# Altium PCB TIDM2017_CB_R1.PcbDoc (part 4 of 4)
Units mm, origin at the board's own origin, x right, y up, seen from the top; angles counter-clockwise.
Board outline 120 x 77 mm, 4 copper layers (Top Layer, Layer 1, Layer 2, Bottom Layer), stack 1.856 mm thick; 246 components, 167 nets, 1255 pads, 326 vias.
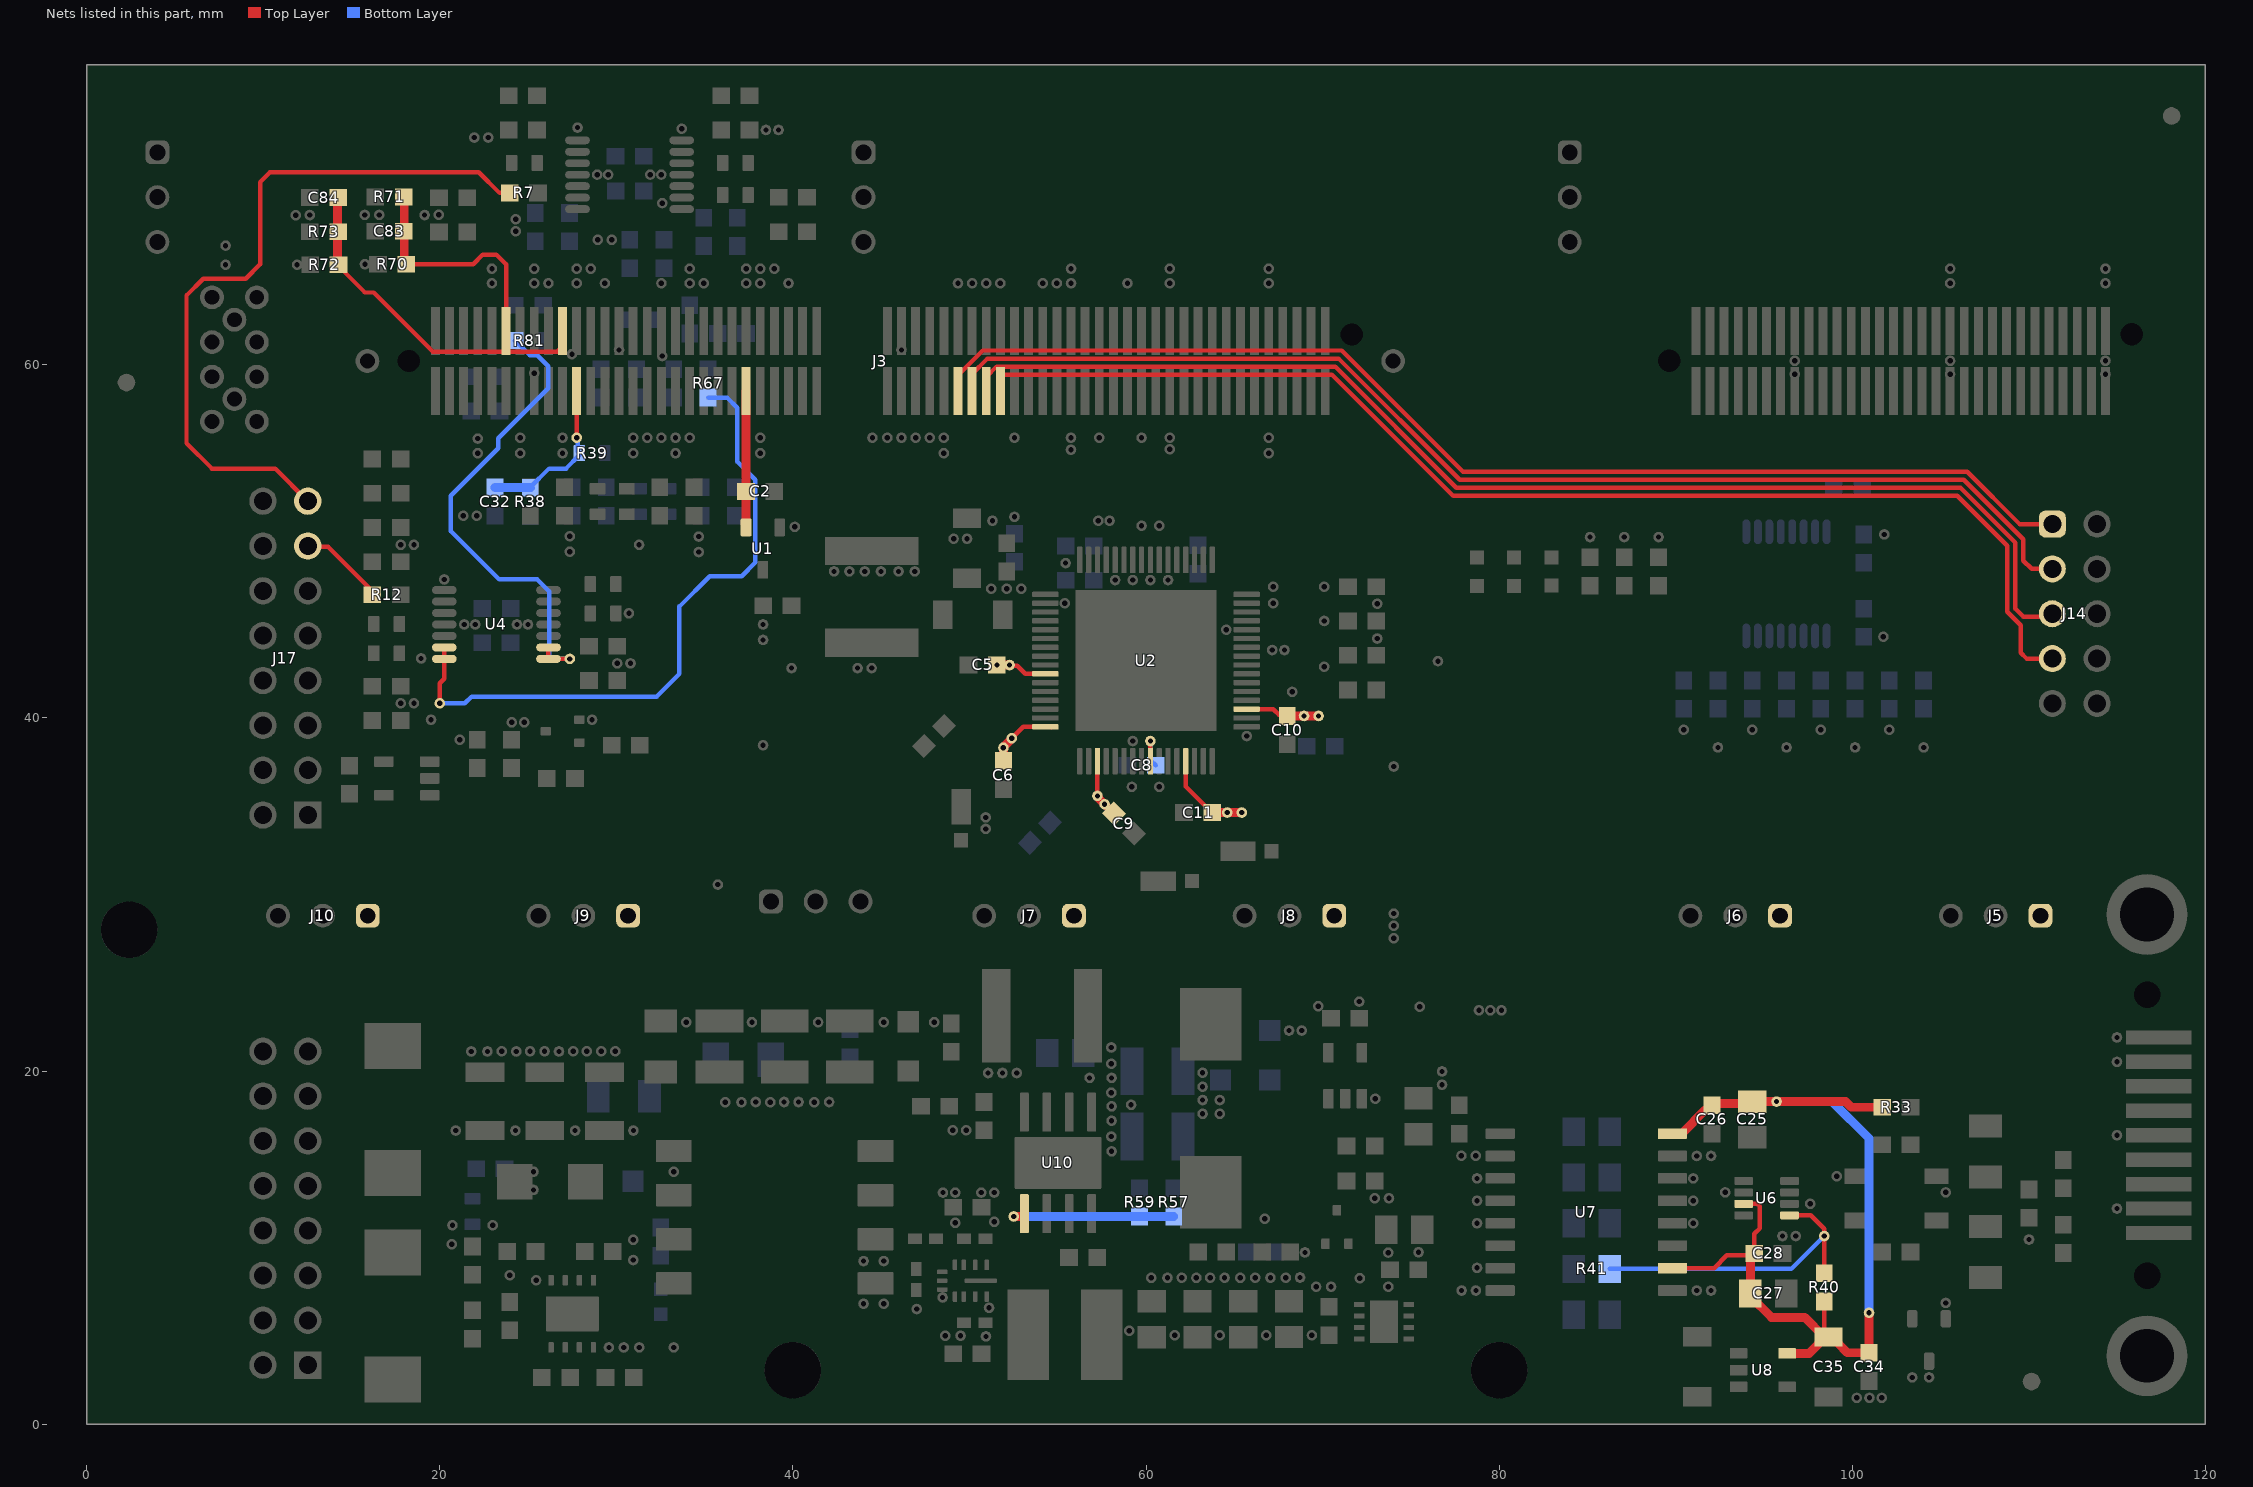
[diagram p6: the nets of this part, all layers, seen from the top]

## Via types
v1: diameter 0.6, hole 0.3, Top Layer to Bottom Layer, 276 vias
v2: diameter 0.5, hole 0.2, Top Layer to Bottom Layer, 40 vias
v3: diameter 0.63, hole 0.33, Top Layer to Bottom Layer, tented both sides, 6 vias
v4: diameter 0.5, hole 0.2, Top Layer to Bottom Layer, tented both sides, 4 vias

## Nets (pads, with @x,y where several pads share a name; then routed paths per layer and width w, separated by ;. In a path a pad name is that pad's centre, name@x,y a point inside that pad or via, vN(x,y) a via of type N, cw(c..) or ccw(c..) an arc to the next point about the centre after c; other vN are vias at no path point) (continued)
NetR57_1: pad.2@52.51,11.761 R57.1 R59.2 U10.5 | length 9.8
  Top Layer w0.5: pad.2@52.51,11.761 53.11,11.761 U10.5@53.11,11.924
  Bottom Layer w0.5: pad.2@52.51,11.761 R59.2@59.634,11.761 R57.1@61.573,11.761
NetR67_1: pad.2@20,40.829 R67.1 U4.6 U4.7 | length 37.8
  Top Layer w0.254: pad.2@20,40.829 20,41.961 20.255,42.215 U4.7@20.255,43.344 U4.6@20.255,43.994
  Bottom Layer w0.254: pad.2@20,40.829 21.416,40.829 21.799,41.212 32.287,41.212 33.574,42.499 33.574,46.316 35.287,48.029 37.096,48.029 37.875,48.808 37.875,53.492 36.844,54.523 36.844,57.574 36.27,58.148 R67.1@35.194,58.148
NetR81_1: pad.2@27.364,43.344 R81.1 U4.8 U4.9 | length 27.9
  Top Layer w0.254: U4.9@26.155,43.994 U4.8@26.155,43.344 pad.2@27.364,43.344
  Bottom Layer w0.254: R81.1@24.253,61.375 24.278,61.375 25.103,60.55 25.521,60.55 26.15,59.922 26.15,58.682 23.306,55.838 23.306,55.269 20.625,52.588 20.625,50.588 23.369,47.844 25.514,47.844 26.184,47.173 26.184,43.493 26.333,43.344 pad.2@27.364,43.344
P5V_BATT: C25.1 C26.1 C27.1 C28.1 C34.1 C35.1 pad.2@95.716,18.271 pad.2@100.955,6.31 R33.2 R40.2 U6.3 U7.10 U7.16 U8.5 | length 54.6
  Top Layer w0.254: U7.10@89.816,8.838 92.182,8.838 92.901,9.557 94.344,9.557 C28.1@94.452,9.665 94.452,10.775 94.777,11.1 94.777,12.328 94.628,12.477 U6.3@93.851,12.477 ; R40.2@98.418,6.948 98.418,5.179 C35.1@98.66,4.936
  Top Layer w0.5: U7.16@89.816,16.458 90.341,16.458 91.688,17.805 91.834,17.805 92.059,18.03 C26.1@92.059,18.055 92.167,18.163 94.236,18.163 C25.1@94.344,18.271 99.633,18.271 99.957,17.948 R33.2@101.705,17.948 ; C28.1@94.344,9.557 94.236,9.449 94.236,7.235 95.428,6.043 97.303,6.043 98.41,4.936 98.11,4.636 98.11,4.553 97.567,4.009 U8.5@96.317,4.009 ; C35.1@98.66,4.936 98.91,4.936 99.21,4.636 99.21,4.565 99.73,4.045 C34.1@100.955,4.045 pad.2@100.955,6.31
  Bottom Layer w0.5: pad.2@95.716,18.271 98.878,18.271 100.955,16.194 pad.2@100.955,6.31
POS_LDO_SENSE: C83.2 J3.12 R70.2 R71.2 | length 13.9
  Top Layer w0.254: R70.2@18.022,65.705 21.889,65.705 22.434,66.25 23.205,66.25 23.75,65.705 J3.12@23.75,61.919 J3.12@23.832,61.836
  Top Layer w0.5: R71.2@17.947,69.509 17.984,69.472 17.984,65.742 R70.2@18.022,65.705
SHA: C5.1 J10.1 pad.2@51.562,43 pad.2@52.273,42.999 U2.26 | length 3
  Top Layer w0.254: pad.2@52.273,42.999 52.321,42.952 52.704,42.952 53.156,42.5 U2.26@54.3,42.5
  Top Layer w0.5: pad.2@51.562,43 C5.1@51.575,43 ; pad.2@51.562,43 pad.2@52.273,42.999
SHB: C8.1 J7.1 pad.2@60.25,38.692 U2.41 | length 2.6
  Top Layer w0.254: U2.41@60.25,37.55 pad.2@60.25,38.692
  Bottom Layer w0.254: pad.2@60.25,38.692 60.25,37.621 C8.1@60.55,37.321
SHC: C10.1 J6.1 pad.2@68.95,40.111 pad.2@69.776,40.111 U2.51 | length 4.2
  Top Layer w0.254: U2.51@65.7,40.5 67.215,40.5 67.529,40.186 67.929,40.186 C10.1@68.004,40.111
  Top Layer w0.5: C10.1@68.004,40.111 pad.2@68.95,40.111 pad.2@69.776,40.111
SLA: C6.1 J9.1 pad.2@51.922,38.317 pad.2@52.397,38.853 U2.32 | length 4
  Top Layer w0.254: pad.2@52.397,38.853 53.044,39.5 U2.32@54.3,39.5 54.604,39.5 U2.32@54.627,39.477
  Top Layer w0.5: C6.1@51.922,37.567 pad.2@51.922,38.317 51.922,38.344 52.378,38.8 52.378,38.834 pad.2@52.397,38.853
SLB: C9.1 J8.1 pad.2@57.25,35.583 pad.2@57.654,35.112 U2.35 | length 3.4
  Top Layer w0.254: pad.2@57.25,35.583 U2.35@57.25,37.55
  Top Layer w0.5: pad.2@57.25,35.583 57.25,35.556 57.3,35.506 57.3,35.466 C9.1@58.184,34.582
SLC: C11.1 J5.1 pad.2@64.604,34.642 pad.2@65.43,34.642 U2.45 | length 5.2
  Top Layer w0.254: U2.45@62.25,37.55 62.25,36.117 63.725,34.642 C11.1@63.75,34.642
  Top Layer w0.5: C11.1@63.75,34.642 pad.2@65.43,34.642
SPIA_CLK: J3.71 J14.5 | length 69.5
  Top Layer w0.254: J3.71@50.95,58.519 50.982,58.55 50.982,59.351 51.537,59.906 70.717,59.906 77.58,53.043 106.136,53.043 109.242,49.937 109.242,46.199 109.696,45.745 111.177,45.745 J14.5@111.335,45.903
SPIA_SIMO: J3.67 J14.1 | length 67.5
  Top Layer w0.254: J3.67@49.35,58.519 49.35,59.412 50.751,60.814 71.093,60.814 77.956,53.951 106.513,53.951 109.481,50.983 J14.1@111.335,50.983
SPIA_SOMI: J3.69 J14.3 | length 68.2
  Top Layer w0.254: J3.69@50.15,58.519 50.16,58.529 50.16,59.5 51.021,60.36 70.905,60.36 77.768,53.497 106.324,53.497 109.696,50.125 109.696,48.912 110.166,48.443 J14.3@111.335,48.443
SPIA_STE: J3.73 J14.7 | length 70.3
  Top Layer w0.254: J3.73@51.846,58.615 J3.73@51.75,58.519 51.725,58.543 51.725,59.244 51.933,59.452 70.529,59.452 77.392,52.589 105.948,52.589 108.788,49.749 108.788,46.011 109.548,45.252 109.548,43.693 109.878,43.363 J14.7@111.335,43.363
THROTTLE_1: J17.15 R7.1 | length 41.4
  Top Layer w0.254: J17.15@12.52,52.28 10.675,54.125 7.094,54.125 5.65,55.569 5.65,63.93 6.604,64.884 8.999,64.884 9.815,65.7 9.815,70.35 10.38,70.915 22.208,70.915 23.383,69.74 24.037,69.74 24.037,69.816 R7.1@23.839,70.014
THROTTLE_2: J17.13 R12.1 | length 5
  Top Layer w0.254: J17.13@12.52,49.74 12.575,49.685 13.676,49.685 16.257,47.104 R12.1@16.257,46.979
THROTTLE_LDO_SENSE: C84.2 J3.20 R72.2 R73.2 | length 19.7
  Top Layer w0.254: R72.2@14.187,65.671 14.187,65.546 14.385,65.348 14.51,65.348 15.76,64.099 16.257,64.099 19.6,60.757 26.638,60.757 26.95,61.068 J3.20@26.95,61.919
  Top Layer w0.5: R72.2@14.187,65.671 14.212,65.696 14.212,69.451 C84.2@14.238,69.476
VDC: C32.2 J3.21 pad.2@27.75,55.875 R38.2 R39.2 | length 9.3
  Top Layer w0.254: pad.2@27.75,55.875 J3.21@27.75,58.519
  Bottom Layer w0.254: R38.2@25.128,53.044 25.128,53.069 26.184,54.125 27.15,54.125 27.9,54.875 R39.2@27.9,55 27.816,55.084 27.816,55.809 pad.2@27.75,55.875
  Bottom Layer w0.5: C32.2@23.125,53.05 23.128,53.047 25.125,53.047 R38.2@25.128,53.044
VIO: pad.2@98.418,10.653 R40.1 R41.2 U6.5 | length 17.7
  Top Layer w0.254: U6.5@96.451,11.827 97.66,11.827 98.418,11.069 pad.2@98.418,10.653 R40.1@98.418,8.548
  Bottom Layer w0.254: R41.2@86.266,8.788 96.552,8.788 pad.2@98.418,10.653
VREF: C2.2 J3.45 U1.2 | length 7.8
  Top Layer w0.5: U1.2@37.344,50.76 37.35,50.766 J3.45@37.35,58.519
pads on no net: FID1.1 FID2.1 FID3.1 J3.1 J3.2 J3.14 J3.17 J3.23 J3.30 J3.32 J3.36 J3.39 J3.41 J3.42 J3.43 J3.44 J3.54 J3.56 J3.62 J3.64 J3.66 J3.76 J3.78 J3.85 J3.86 J3.88 J3.89 J3.90 J3.91 J3.96 J3.100 J3.102 J3.104 J3.105 J3.106 J3.107 J3.108 J3.109 J3.113 J3.114 J3.115 J3.116 J3.117 J3.118 J3.119 J3.181 J3.182 J3.185 J3.186 J4.61 J4.62 J4.121 J4.122 J4.123 J4.124 J4.125 J4.126 J4.127 J4.128 J4.129 J4.130 J4.131 J4.132 J4.133 J4.134 J4.136 J4.137 J4.138 J4.139 J4.140 J4.141 J4.142 J4.143 J4.144 J4.145 J4.146 J4.147 J4.148 J4.149 J4.150 J4.151 J4.152 J4.153 J4.154 J4.155 J4.156 J4.159 J4.160 J4.161 J4.162 J4.163 J4.164 J4.165 J4.166 J4.167 J4.168 J4.169 J4.170 J4.171 J4.172 J4.173 J4.174 J4.175 J4.176 J4.177 J4.178 J5.3 J8.3 J9.3 J15.4 J15.5 J15.8 J15.MH LBL1.0 U2.16 U2.21 U2.22 U2.24 U2.29 U2.30 U2.37 U2.38 U2.43 U2.47 U2.48 U2.54 U2.55 U2.56 U2.57 U4.12 U4.13 U4.14 U5.1 U5.3 U5.14 U5.16 U7.6 U7.11 U8.2 U9.9@26.749,6.246 U9.9@28.259,6.246 U10.6 U11.8

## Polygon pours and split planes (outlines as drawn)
SLC on Layer 1 "LAYER_1_SLC_P006" (solid, remove dead copper, pour order 6): 61.3,33.68 63.75,31.23 63.75,31.21 69.457,31.21 71.927,33.68 101.548,33.68 104.316,30.912 104.316,27.528 111.936,27.528 111.936,30.27 104.956,37.25 66.195,37.25 65.1,38.345 61.3,38.344
GND on Layer 1 "LAYER_1_GND_P041" (solid, remove dead copper, pour order 41): 1.375,10.061 17.832,10.061 17.832,21.477 19.883,23.528 34.484,23.528 34.484,17.666 34.634,17.516 43.687,17.516 43.687,5.003 44.961,3.729 74.718,3.729 77.913,6.923 79.791,6.923 79.791,18.687 83.56,22.456 110.923,22.456 113.605,25.138 113.605,31.261 118.594,36.251 118.594,75.971 1.375,75.971 1.375,27.528 9.021,27.575 9.021,31.093 10.474,32.545 16.886,32.545 21.091,36.75 41.209,36.75 41.209,36.766 48.98,44.536 52.761,44.536 53.496,43.802 55.636,43.802 55.636,47.206 55.998,47.568 63.898,47.568 64.234,47.233 64.234,39.61 66.355,37.488 105.242,37.488 112.063,30.668 112.063,27.179 101.921,27.179 100.801,27.179 99.514,27.179 1.375,27.179
GND_BATT on Layer 1 "LAYER_1_GND_BATT_P014" (solid, remove dead copper, pour order 14): 88.681,4.249 83.55,4.249 81.425,6.374 78.504,6.374 74.817,2.687 45.445,2.687 41.149,6.983 34.273,6.983 34.273,16.797 33.405,17.665 33.405,20.51 19.305,20.51 19.312,20.503 19.312,9.346 1.375,9.346 1.375,0.75 119.25,0.75 119.5,1 119.5,31.859 114.524,31.859 113.872,31.207 113.872,22.139 111.233,19.5 88.681,19.5
SLA on Layer 1 "LAYER_1_SLA_P000" (solid, remove dead copper, pour order 0): 24.125,27.456 32.689,27.456 32.689,30.839 33.26,31.41 47.312,31.41 50.636,34.734 52.735,34.734 54.75,36.75 56.25,36.75 56.25,38.595 56.095,38.75 55.026,38.75 55.026,40.757 51.399,40.757 44.326,33.684 28.184,33.684 24.125,29.625
SHA on Layer 1 "LAYER_1_SHA_P001" (solid, remove dead copper, pour order 1): 10.508,32.25 17.108,32.25 21.266,36.408 41.371,36.408 48.436,43.473 49.199,44.25 52.471,44.25 53.248,43.473 54.133,43.473 55.026,43.5 55.026,41 51.225,41 44.253,34.028 23.528,34.028 18.75,29.25 18.75,26.75 9.25,26.75 9.25,30.992
SLB on Layer 1 "LAYER_1_SLB_P004" (solid, remove dead copper, pour order 4): 59.865,27.048 71.936,27.048 71.936,30.985 63.194,30.985 58.25,35.929 58.25,38.378 56.436,38.378 56.436,36.651 55.725,35.94 55.725,31.189
GND on Layer 2 "LAYER_2_GND_P038" (solid, remove dead copper, pour order 38): 112.942,32.933 112.875,32.866 112.875,24.526 110.598,22.25 102.259,22.25 83.402,22.25 79.791,18.639 79.791,6.923 77.913,6.923 74.718,3.729 44.961,3.729 43.687,5.003 43.687,17.516 34.634,17.516 34.491,17.659 34.491,22.134 31.33,22.134 31.295,22.169 31.295,23.528 19.883,23.528 17.832,21.477 17.832,10.061 1.375,10.061 1.375,27.048 96.96,27.048 97.605,27.694 97.605,29.799 84.545,42.859 64.234,42.859 64.234,47.233 63.898,47.568 55.998,47.568 55.636,47.206 55.636,38.957 47.848,31.169 47.848,27.528 1.375,27.528 1.375,75.971 118.594,75.971 118.594,38.585 116.634,36.625
GND_BATT on Layer 2 "LAYER_2_GND_BATT_P013" (solid, remove dead copper, pour order 13): 88.681,4.249 83.55,4.249 81.425,6.374 78.504,6.374 74.817,2.687 45.445,2.687 41.149,6.983 34.273,6.983 34.273,16.797 33.405,17.665 33.405,20.51 30.661,20.51 30.661,22.694 20.319,22.694 19.312,21.687 19.312,9.346 1.375,9.346 1.375,0.75 88.681,0.75 119.25,0.75 119.5,1 119.5,31.859 114.524,31.859 113.872,31.207 113.872,22.139 111.233,19.5 88.681,19.5
SHC on Layer 2 "LAYER_2_SHC_P007" (solid, remove dead copper, pour order 7): 64.843,42.307 84.132,42.307 97.036,29.404 97.036,27.678 89.572,27.678 80.31,36.94 65.064,36.94 64.843,37.162
SHB on Layer 2 "LAYER_2_SHB_P005" (solid, remove dead copper, pour order 5): 57.36,39.258 52.836,34.734 48.955,30.853 48.955,27.528 58.117,27.528 61.349,30.76 61.349,31.21 61.349,39.258
+12V on Top Layer "TOP_LAYER_+12V_P042" (solid, remove dead copper, pour order 42): 50.49,7.576 50.49,6.495 49.949,5.954 49.949,4.729 49.677,4.457 49.677,3.507 48.112,3.507 48.112,5.649 48.649,5.649 49.508,6.508 49.508,7.569
+12V on Top Layer "TOP_LAYER_+12V_P045" (solid, remove dead copper, pour order 45): 48.031,13.579 49.677,13.579 49.677,11.411 50.299,10.789 50.299,10.189 49.105,10.189 48.692,10.602 48.031,11.263
GND on Top Layer "TOP_LAYER_GND_P044" (solid, remove dead copper, pour order 44): 50.188,11.615 50.188,13.579 51.948,13.579 51.948,9.6 51.092,8.744 50.812,8.744 50.812,9.645 50.472,9.985 50.472,11.331
GND on Top Layer "TOP_LAYER_GND_P043" (solid, remove dead copper, pour order 43): 50.827,7.546 51.108,7.546 51.402,7.252 51.402,3.257 50.182,3.257 50.182,4.644 50.518,4.98 50.518,6.136 50.827,6.445
NetC12_1 on Top Layer "TOP_LAYER_NETC12_1_P024" (solid, remove dead copper, pour order 24): 51.752,7.546 51.402,7.896 49.726,7.896 49.726,8.293 53.835,8.293 54.555,7.573 54.555,2.321 51.752,2.321
+3.3V on Top Layer "TOP_LAYER_+3.3V_P035" (solid, remove dead copper, pour order 35): 74.949,12.024 76.494,12.024 76.494,4.854 76.249,4.609 74.624,4.609 74.624,5.051 74.635,5.062 75.432,5.062 75.432,7.467 74.881,8.019 74.949,8.087
+12_48 on Top Layer "TOP_LAYER_+12_48_P034" (solid, remove dead copper, pour order 34): 61.703,24.746 65.598,24.746 65.598,17.656 65.197,17.255 61.703,17.255
GND on Top Layer "TOP_LAYER_GND_P033" (solid, remove dead copper, pour order 33): 58.523,25.76 58.523,14.94 57.515,14.94 57.515,16.479 56.525,16.479 56.525,19.614 55.711,20.428 55.711,25.76
+48V on Top Layer "TOP_LAYER_+48V_P032" (solid, remove dead copper, pour order 32): 53.635,19.324 54.168,18.791 54.168,16.799 54.168,16.639 55.875,16.639 55.875,19.197 52.331,22.741 52.331,26.046 49.886,26.046 45.371,30.56 40.528,30.56 40.528,28.796 44.163,28.796 50.182,22.777 50.182,19.529 50.387,19.324
GND on Top Layer "TOP_LAYER_GND_P027" (solid, remove dead copper, pour order 27): 70.817,6.134 70.807,6.124 69.004,6.124 68.819,6.309 59.308,6.309 59.308,8.788 72.781,8.788 72.781,11.988 72.744,12.024 74.267,12.024 74.267,8.466 75.274,7.459 75.274,5.289 74.624,5.289 74.624,7.092 74.366,7.349 70.817,7.349
+5V on Top Layer "TOP_LAYER_+5V_P026" (solid, remove dead copper, pour order 26): 71.461,5.024 71.461,4.994 72.365,4.994 72.37,4.999 72.37,4.249 70.996,4.249 59.477,4.249 58.909,3.68 58.909,2.321 56.315,2.321 56.283,2.354 56.283,7.748 58.909,7.748 58.909,5.724 58.983,5.649 70.836,5.649
NetC50_2 on Top Layer "TOP_LAYER_NETC50_2_P025" (solid, remove dead copper, pour order 25): 56.903,12.991 59.692,12.991 61.972,15.272 65.43,15.272 65.43,11.037 58.312,11.037 57.764,10.489 57.769,10.484 57.769,8.959 56.71,8.959 56.71,12.991
GND on Top Layer "TOP_LAYER_GND_P023" (solid, remove dead copper, pour order 23): 43.609,11.224 45.759,11.224 45.759,5.299 45.759,5.08 43.609,5.08
GND on Top Layer "TOP_LAYER_GND_P022" (solid, remove dead copper, pour order 22): 34.491,20.643 34.5,20.634 34.5,17.65 34.65,17.5 42.9,17.5 44.578,19.178 44.578,20.643
+12_Bat_Iso on Top Layer "TOP_LAYER_+12_BAT_ISO_P021" (solid, remove dead copper, pour order 21): 31.33,23.759 31.33,22.134 49.695,22.134 49.695,23.759
NetC36_2 on Top Layer "TOP_LAYER_NETC36_2_P020" (solid, remove dead copper, pour order 20): 45.91,20.643 47.178,20.643 47.178,19.079 47.782,18.475 47.782,17.525 47.235,17.525 45.759,16.049 45.759,12.289 43.627,12.289 43.609,12.271 43.609,17.179 43.709,17.179 45.91,19.38
GND_BATT on Top Layer "TOP_LAYER_GND_BATT_P019" (solid, remove dead copper, pour order 19): 15.436,22.694 30.661,22.694 30.661,19.38 30.666,19.375 15.436,19.375
GND_BATT on Top Layer "TOP_LAYER_GND_BATT_P018" (solid, remove dead copper, pour order 18): 28.485,4.746 31.743,4.746 31.743,1.981 31.677,1.915 30.424,1.915 30.424,3.342 30.186,3.58 28.485,3.58
GND_BATT on Top Layer "TOP_LAYER_GND_BATT_P017" (solid, remove dead copper, pour order 17): 20.25,11.75 24.282,11.75 24.282,9.311 22.731,9.311 22.541,9.5 20.25,9.5
+12V_BAT_PROT on Top Layer "TOP_LAYER_+12V_BAT_PROT_P016" (solid, remove dead copper, pour order 16): 31.42,17.179 31.605,17.364 31.605,20.51 33.405,20.51 33.405,17.665 34.229,16.841 34.229,12.271 34.25,12.25 34.237,12.237 27.381,12.237 27.381,7.896 26.875,7.896 26.875,8.656 26.445,9.086 25,9.086 25,12.25 19,12.25 19,8.42 15.75,8.459 15.75,15.5 17.429,17.179
NetC46_2 on Top Layer "TOP_LAYER_NETC46_2_P015" (solid, remove dead copper, pour order 15): 28.407,8.461 29.257,9.311 29.326,9.311 29.326,11.267 34.208,11.267 34.25,11.224 34.25,7.25 31.743,7.25 31.097,7.896 28.407,7.896
+12V on Top Layer "TOP_LAYER_+12V_P012" (solid, remove dead copper, pour order 12): 53.579,46.841 53.611,46.841 54.9,46.841 54.9,48.202 53.579,48.202
GND on Top Layer "TOP_LAYER_GND_P011" (solid, remove dead copper, pour order 11): 47.322,50.77 50.182,47.911 50.182,46.839 48.854,46.839 47.664,48.029 41.53,48.029 41.53,50.77
GND on Top Layer "TOP_LAYER_GND_P010" (solid, remove dead copper, pour order 10): 52.531,46.789 53.254,46.789 53.254,48.862 51.631,48.862 51.262,48.492 48.907,48.492 48.907,46.789
GND on Top Layer "TOP_LAYER_GND_P008" (solid, remove dead copper, pour order 8): 72.5,48.029 72.5,42.952 73.669,42.952 73.762,42.859 73.762,48.029
+12V on Bottom Layer "BOTTOM_LAYER_+12V_P046" (solid, remove dead copper, pour order 46): 47.144,13.579 49.677,13.579 49.677,9.957 49.695,9.939 48,8.244 48,7.002 50.285,4.718 50.285,3.729 46.434,3.729 46.434,13.579
GND on Bottom Layer "BOTTOM_LAYER_GND_P040" (solid, remove dead copper, pour order 40): 31.295,19.044 31.295,17.68 43.113,17.68 43.703,18.27 43.703,21.394 37.935,21.394 37.967,21.362 37.967,19.457 37.554,19.044 31.624,19.044
GND_BATT on Bottom Layer "BOTTOM_LAYER_GND_BATT_P039" (solid, remove dead copper, pour order 39): 27.128,21.625 27.128,17.65 29.752,17.65 29.752,20.081 34.484,20.081 34.871,19.694 36.375,19.694 36.375,21.625 27.364,21.625
+48V on Bottom Layer "BOTTOM_LAYER_+48V_P031" (solid, remove dead copper, pour order 31): 55.098,21.894 55.098,19.484 50.567,19.484 50.469,19.581 50.469,21.894
GND on Bottom Layer "BOTTOM_LAYER_GND_P030" (solid, remove dead copper, pour order 30): 55.725,21.75 59.865,21.75 59.865,14.94 55.725,14.94 55.725,19.079
+12_48 on Bottom Layer "BOTTOM_LAYER_+12_48_P029" (solid, remove dead copper, pour order 29): 61.349,21.334 63.52,21.334 64.843,20.012 64.843,16.968 62.815,14.94 61.349,14.94
+12_Bat_Iso on Bottom Layer "BOTTOM_LAYER_+12_BAT_ISO_P028" (solid, remove dead copper, pour order 28): 31.33,24 31.33,22.134 49.726,22.134 49.976,22.384 62.991,22.384 63.625,21.75 64.843,21.75 64.843,24

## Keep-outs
Keep-Out Layer:
  text ".Layer_Name" at 14.656,-21.806 h1.5

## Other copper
Top Layer:
  text ".Layer_Name" at 14.656,-21.806 h1.5
Bottom Layer:
  text ".Layer_Name" at 14.656,-21.806 h1.5

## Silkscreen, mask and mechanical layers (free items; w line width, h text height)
Top Overlay:
  lines w0.254: 106.237,38.75 106.237,53.043 117.429,53.043 117.429,38.75 106.237,38.75
  text "'.PRJ_Number'.PCB_Rev" at 98.65,68.152 h1.5
  text "SDI" at 106.76,50.491 h1.5
  text "SDO" at 106.875,47.893 h1.5
  text "CLK" at 106.76,45.411 h1.5
  text "GND" at 116.462,44.52 h1.5 r90
  text "nCS" at 106.875,42.89 h1.5
  text "+5V" at 106.875,40.383 h1.5
  text "POS SPI/DEBUG" at 106.656,37.108 h1.5
  text ".Layer_Name" at 14.656,-21.806 h1.5
Bottom Overlay:
  text ".Layer_Name" at 14.656,-21.806 h1.5
Top Paste:
  text ".Layer_Name" at 14.656,-21.806 h1.5
Bottom Paste:
  text ".Layer_Name" at 14.656,-21.806 h1.5
Top Solder:
  text ".Layer_Name" at 14.656,-21.806 h1.5
  text ".Layer_Name" at 14.656,-21.806 h1.5
Bottom Solder:
  text ".Layer_Name" at 14.656,-21.806 h1.5
Drill Guide:
  text ".Layer_Name" at 14.656,-21.806 h1.5
M1 Board Outline:
  the board outline again, w0.254
  text ".Layer_Name" at 14.656,-21.806 h1.5
M2 Board Dimensions:
  rectangle: 0,-6.985 3.175,-3.81
  rectangle: 3.175,-10.16 12.7,-6.985
  lines w0.178: 0,-6.985 25.4,-6.985 ; 3.175,-10.16 3.175,-3.81 ; 6.35,-10.16 6.35,-3.81 ; 12.7,-10.16 12.7,-3.81 ; 19.05,-10.16 19.05,-3.81 ; 0,-10.16 25.4,-10.16 25.4,-3.81 0,-3.81 0,-10.16
  text ".Layer_Name" at 14.656,-21.806 h1.5
M3 3D STEP Top:
  text ".Layer_Name" at 14.656,-21.806 h1.5
M4 3D STEP Bottom:
  text ".Layer_Name" at 14.656,-21.806 h1.5
M5 Assembly Top:
  lines w0.254: -7.417,-23.626 160.223,-23.626 ; -7.417,-18.462 160.274,-18.462 ; -7.417,-13.297 -7.417,-28.791 94.31,-28.791 160.274,-28.791 160.274,-13.297 -7.404,-13.297 -7.404,-28.791 32.614,-28.791 ; 55.194,-28.791 55.194,-13.297 ; 87.376,-18.462 87.376,-13.297 ; 108.712,-18.462 108.712,-13.297 ; 124.511,-28.956 124.511,-23.804
  text "COMPONENTS MARKED 'DNP' SHOULD NOT BE POPULATED." at 29.299,-8.09 h1.5
  text "ASSEMBLY VARIANT:" at 29.286,-11.024 h1.5
  text ".VariantName" at 55.601,-11.024 h1.5
  text "PCB VIEWED FROM TOP SIDE" at -5.804,-16.654 h1.5
  text "BOARD #:" at 57.099,-16.654 h1.5
  text ".PRJ_Number" at 70.955,-16.654 h1.5
  text "REV:" at 92.405,-16.654 h1.5
  text ".PCB_Rev" at 99.809,-16.654 h1.5
  text "SVN REV:" at 113.69,-16.654 h1.5
  text ".VersionControl_RevNumber" at 126.543,-16.654 h1.5
  text "TID #:" at 57.099,-21.819 h1.5
  text ".TID" at 70.955,-21.819 h1.5
  text "PLOT NAME =" at -5.804,-27.034 h1.5
  text ".plot_File_Name" at 14.656,-27.034 h1.5
  text "GENERATED    :" at 57.15,-27.034 h1.5
  text ".Print_Date" at 79.235,-27.034 h1.5
  text ".Print_Time" at 97.752,-27.034 h1.5
  text "TEXAS INSTRUMENTS" at 129.87,-27.034 h1.5
M6 Assembly Bottom:
  lines w0.254: -7.429,-18.474 160.261,-18.474 ; -7.379,-23.639 160.261,-23.639 ; 28.334,-28.969 28.334,-23.817 ; 44.133,-18.474 44.133,-13.31 ; 65.468,-18.474 65.468,-13.31 ; 97.65,-28.804 97.65,-13.31 ; 120.231,-28.804 160.249,-28.804 160.249,-13.31 -7.429,-13.31 -7.429,-28.804 58.534,-28.804 160.261,-28.804 160.261,-13.31
  text "COMPONENTS MARKED 'DNP' SHOULD NOT BE POPULATED." at 154.991,-8.077 h1.5
  text ".VariantName" at 128.473,-11.024 h1.5
  text "ASSEMBLY VARIANT:" at 154.864,-11.024 h1.5
  text ".VersionControl_RevNumber" at 26.302,-16.667 h1.5
  text "SVN REV:" at 39.154,-16.667 h1.5
  text ".PCB_Rev" at 53.035,-16.667 h1.5
  text "REV:" at 60.439,-16.667 h1.5
  text ".PRJ_Number" at 81.89,-16.667 h1.5
  text "BOARD #:" at 95.745,-16.667 h1.5
  text "PCB VIEWED FROM BOTTOM SIDE" at 158.648,-16.667 h1.5
  text ".TID" at 81.89,-21.831 h1.5
  text "TID #:" at 95.745,-21.831 h1.5
  text "TEXAS INSTRUMENTS" at 22.974,-27.047 h1.5
  text ".Print_Time" at 55.093,-27.047 h1.5
  text ".Print_Date" at 73.609,-27.047 h1.5
  text "GENERATED    :" at 95.694,-27.047 h1.5
  text ".plot_File_Name" at 138.189,-27.047 h1.5
  text "PLOT NAME =" at 158.648,-27.047 h1.5
M9 Title Sheet:
  drawing of 57 lines, arcs and shapes, not listed
  text "1" at 18.792,204.127 h1.5
  text "2" at 82.182,204.127 h1.5
  text "3" at 145.411,204.127 h1.5
  text "4" at 209.08,204.127 h1.5
  text "5" at 272.555,204.127 h1.5
  text "6" at 336.182,204.127 h1.5
  text "A" at -10.579,175.095 h1.5
  text "A" at 365.341,175.095 h1.5
  text "B" at -10.579,114.643 h1.5
  text "B" at 365.341,114.643 h1.5
  text "C" at -10.579,54.318 h1.5
  text "C" at 365.341,54.318 h1.5
  text "PROJECT TITLE:" at 288.125,7.048 h1.5
  text ".PRJ_Title" at 289.395,3.662 h1.5
  text "DESIGNED FOR:" at 288.125,-0.597 h1.5
  text ".PRJ_Customer" at 289.395,-4.153 h1.5
  text "D" at -10.579,-5.88 h1.5
  text "D" at 365.341,-5.88 h1.5
  text "FILE NAME:" at 288.125,-8.217 h1.5
  text ".PCB_File_Name_No_Path" at 289.395,-11.265 h1.5
  text "Texas Instruments (TI) and/or its licensors do not warrant the accuracy or completeness of this specification" at 161.9,-15.376 h1.5
  text "ENGINEER:" at 288.125,-15.583 h1.5
  text "LAYOUT BY:" at 326.352,-15.583 h1.5
  text "or any information contained therein. TI and/or its licensors do not warrant that this design will meet" at 160.757,-18.237 h1.5
  text ".PRJ_Engineer" at 289.395,-19.52 h1.5
  text ".PCB_Layout" at 327.635,-19.52 h1.5
  text "the specifications, will be suitable for your application or fit for any particular purpose, or will operate in" at 160.757,-21.099 h1.5
  text ".Layer_Name" at 14.656,-21.806 h1.5
  text "ALTIUM DESIGNER VERSION:" at 326.352,-23.457 h1.5
  text "an implementation. TI and/or its licensors do not warrant that the design is production worthy. You should" at 160.757,-23.961 h1.5
  text "completely validate and test your design implementation to confirm the system functionality for your application." at 161.9,-26.822 h1.5
  text ".print_Scale" at 289.395,-26.843 h1.5
  text ".Application_BuildNumber" at 327.635,-26.843 h1.5
  text "1" at 18.792,-32.093 h1.5
  text "2" at 82.182,-32.093 h1.5
  text "3" at 145.411,-32.093 h1.5
  text "4" at 209.08,-32.093 h1.5
  text "5" at 272.555,-32.093 h1.5
  text "6" at 336.182,-32.093 h1.5
M10 Fab Notes:
  drawing of 189 lines, arcs and shapes, not listed
  text "DESIGN INFORMATION" at 314.503,161.447 h1.5
  text "MIN. TRACK WIDTH:" at 298.131,158.091 h1.5
  text "8" at 325.976,158.091 h1.5
  text "MIL" at 329.907,158.091 h1.5
  text "7.874" at 321.75,155 h1.5
  text "MIN. CLEARANCE:" at 298.131,154.938 h1.5
  text "MIL" at 329.907,154.938 h1.5
  text "MIN. VIA PAD SIZE:" at 298.131,151.785 h1.5
  text "24" at 325.214,151.785 h1.5
  text "MIL" at 329.907,151.785 h1.5
  text "0.05mm (2MIL)" at 315.784,148.486 h1.5
  text "MINIMUM ANNULAR RING" at 289.769,148.277 h1.5
  text "EXTERNAL" at 333.768,148.277 h1.5
  text "PER" at 294.849,145.48 h1.5
  text "IPC-D-275 CLASS 2 LEVEL C" at 300.437,145.48 h1.5
  text "MIL, HOLES" at 338.238,142.928 h1.5
  text "+/-" at 328.27,142.709 h1.5
  text "+/-" at 349.961,142.709 h1.5
  text "REGISTRATION TOLERANCES:" at 289.769,142.682 h1.5
  text "METAL" at 320.243,142.682 h1.5
  text "5" at 334.879,142.683 h1.5
  text "3" at 356.037,142.683 h1.5
  text "MIL" at 358.99,142.682 h1.5
  text "HOLE SIZE TOLERANCE (UNLESS OTHERWISE SPECIFIED):" at 289.769,140.185 h1.5
  text "+/-" at 349.961,140.112 h1.5
  text "3" at 356.037,140.085 h1.5
  text "MIL" at 358.99,140.085 h1.5
  text "MATERIAL:" at 287.87,136.589 h1.5
  text "FR-4 High Tg" at 312.926,133.324 h1.5
  text "X" at 309.257,133.122 h1.5
  text "FR-4" at 298.563,133.007 h1.5
  text "OTHER" at 336.358,133.007 h1.5
  text "62 MIL (1.6mm) +/-10%" at 306.694,129.374 h1.5
  text "X" at 303.643,129.312 h1.5
  text "THICKNESS:" at 289.769,129.165 h1.5
  text "OTHER" at 339.33,129.165 h1.5
  text "TOLERANCE:" at 289.769,125.652 h1.5
  text "X" at 311.314,125.652 h1.5
  text "ANSI IPC-6012 TYPE 3 CLASS 2" at 315.836,125.652 h1.5
  text "OTHER +/-" at 315.835,121.989 h1.5
  text "BOW & TWIST:" at 289.769,118.302 h1.5
  text "X" at 311.314,118.302 h1.5
  text "ANSI IPC-6012 TYPE 3 CLASS 2" at 315.836,118.302 h1.5
  text "OTHER +/-" at 315.835,114.576 h1.5
  text "DRILLING:" at 287.87,111.258 h1.5
  text "NC_DRILL FILES" at 332.599,108.586 h1.5
  text "REFERENCE:" at 289.769,108.486 h1.5
  text "X" at 306.463,108.484 h1.5
  text "AS SHOWN" at 310.984,108.486 h1.5
  text "X" at 329.348,108.486 h1.5
  text "OTHER" at 340.168,104.873 h1.5
  text "PTH COPPER THICKNESS:" at 289.761,104.783 h1.5
  text "X" at 318.697,104.783 h1.5
  text "20-30 um" at 321.948,104.783 h1.5
  text "BOARD FINISH:" at 287.87,101.034 h1.5
  text "SILKSCREEN:" at 291.812,98.237 h1.5
  text "X" at 316.14,98.237 h1.5
  text "TOP" at 319.112,98.237 h1.5
  text "X" at 329.094,98.237 h1.5
  text "BOTTOM" at 332.091,98.237 h1.5
  text "SILKSCREEN COLOR:" at 291.812,94.295 h1.5
  text "X" at 316.115,94.295 h1.5
  text "WHITE" at 319.112,94.295 h1.5
  text "OTHER" at 332.091,94.295 h1.5
  text "X" at 319.442,90.652 h1.5
  text "GREEN" at 322.439,90.652 h1.5
  text "OTHER" at 338.136,90.652 h1.5
  text "SOLDER RESIST COLOR:" at 291.812,90.477 h1.5
  text "X" at 319.442,86.734 h1.5
  text "MATTE" at 322.439,86.734 h1.5
  text "SEMI-GLOSS" at 338.125,86.717 h1.5
  text "IMMERSION GOLD (ENIG)" at 314.819,82.345 h1.5
  text "ENEPIG" at 348.793,82.162 h1.5
  text "SURFACE FINISH:" at 287.87,82.136 h1.5
  text "X" at 310.298,82.136 h1.5
  text "IMM. TIN/SILVER OR EQUIV" at 296.24,78.649 h1.5
  text "OTHER" at 332.599,78.549 h1.5
  text "ARRAY/PANEL:" at 287.87,74.602 h1.5
  text "CUT AND TRIM PER M1 BOARD OUTLINE" at 314.819,74.393 h1.5
  text "N.C. ROUTE" at 314.819,70.94 h1.5
  text "X" at 332.295,70.94 h1.5
  text "V. SCORE" at 336.816,70.94 h1.5
  text "CERTIFICATION:" at 287.87,67.66 h1.5
  text "MATERIALS AND WORKMANSHIP FOR ALL PCBS" at 306.285,67.66 h1.5
  text "TO MEET OR EXCEED THE REQUIREMENTS OF:" at 306.285,65.271 h1.5
  text "X" at 297.078,62.003 h1.5
  text "ANSI IPC-A-600F CLASS ->" at 300.329,62.003 h1.5
  text "X" at 342.188,62.003 h1.5
  text "2" at 344.982,62.003 h1.5
  text "1" at 336.981,61.965 h1.5
  text "3" at 353.973,61.965 h1.5
  text "X" at 317.702,58.252 h1.5
  text "RoHS" at 320.953,58.252 h1.5
  text "OTHER" at 337.321,58.252 h1.5
  text "PER ORDER" at 347.407,58.252 h1.5
  text "ALL BOARDS MUST MEET OR EXCEED UL94-V0 REQUIREMENTS." at 288.569,54.345 h1.5
  text "PCB MUST BEAR THE UL94V-0 UL REGISTERED MATERIAL ID NUMBER" at 288.569,51.397 h1.5
  text "ADDITIONAL REQUIREMENTS:" at 287.87,47.094 h1.5
  text "MICROSECTION:" at 289.769,44.373 h1.5
  text "YES" at 312.775,44.373 h1.5
  text "REQUIRED" at 334.657,40.707 h1.5
  text "BARE BOARD ELEC. TEST:" at 289.769,40.634 h1.5
  text "NONE" at 322.935,40.634 h1.5
  text "X" at 331.66,40.634 h1.5
  text "PER ORDER" at 349.693,40.634 h1.5
  text "XX MIL VIAS REQUIRE NON-CONDUCTIVE FILL AND PLANARIZE" at 294.04,35.428 h1.5
  text "XX MIL VIAS REQUIRE CONDUCTIVE FILL AND PLANARIZE" at 294.243,32.787 h1.5
  text "OUTER XX MIL TRACES REQUIRE 50 OHM SINGLE-ENDED IMPEDANCE" at 294.218,28.637 h1.5
  text "LAYER 2 & 3 (INNER LAYERS) XX MIL WIDE, XX MIL SPACE / TRACES REQUIRE 100 OHM DIFFERENTIAL IMPEDANCE" at 294.015,22.65 h1.5
  text ".Layer_Name" at 14.656,-21.806 h1.5
M11 Gerber Information:
  lines w0.254: -7.417,-23.626 160.223,-23.626 ; -7.417,-18.462 160.274,-18.462 ; -7.417,-13.297 -7.417,-28.791 94.31,-28.791 160.274,-28.791 160.274,-13.297 -7.404,-13.297 -7.404,-28.791 32.614,-28.791 ; 55.194,-28.791 55.194,-13.297 ; 87.376,-18.462 87.376,-13.297 ; 108.712,-18.462 108.712,-13.297 ; 124.511,-28.956 124.511,-23.804
  text "ALL ARTWORK VIEWED FROM TOP SIDE" at -5.804,-16.654 h1.5
  text "BOARD #:" at 57.099,-16.654 h1.5
  text ".PRJ_Number" at 70.955,-16.654 h1.5
  text "REV:" at 92.405,-16.654 h1.5
  text ".PCB_Rev" at 99.809,-16.654 h1.5
  text "SVN REV:" at 113.69,-16.654 h1.5
  text ".VersionControl_RevNumber" at 126.543,-16.654 h1.5
  text "LAYER NAME =" at -5.804,-21.806 h1.5
  text "TID #:" at 57.099,-21.819 h1.5
  text ".TID" at 70.955,-21.819 h1.5
  text "PLOT NAME =" at -5.804,-27.034 h1.5
  text ".plot_File_Name" at 14.656,-27.034 h1.5
  text "GENERATED    :" at 57.15,-27.034 h1.5
  text ".Print_Date" at 79.235,-27.034 h1.5
  text ".Print_Time" at 97.752,-27.034 h1.5
  text "TEXAS INSTRUMENTS" at 129.87,-27.034 h1.5
M12 Stackup:
  drawing of 196 lines, arcs and shapes, not listed
  text "Layer" at 249.19,200.06 h1.5
  text "Name" at 255.684,200.06 h1.5
  text "Material" at 268.551,200.06 h1.5
  text "Thickness" at 280.062,200.06 h1.5
  text "Constant" at 289.529,200.06 h1.5
  text "Board Layer Stack" at 298.262,200.06 h1.5
  text "Top Overlay" at 255.684,197.06 h1.5
  text "Top Solder" at 255.684,194.06 h1.5
  text "Solder Resist" at 268.551,194.06 h1.5
  text "0.40mil" at 280.062,194.06 h1.5
  text "3.5" at 289.529,194.06 h1.5
  text "1" at 249.19,191.06 h1.5
  text "Top Layer" at 255.684,191.06 h1.5
  text "2.76mil" at 280.062,191.06 h1.5
  text "Dielectric 1" at 255.684,188.06 h1.5
  text "PP-006" at 268.551,188.06 h1.5
  text "2.80mil" at 280.062,188.06 h1.5
  text "4.1" at 289.529,188.06 h1.5
  text "2" at 249.19,185.06 h1.5
  text "Layer 1" at 255.684,185.06 h1.5
  text "CF-004" at 268.551,185.06 h1.5
  text "1.38mil" at 280.062,185.06 h1.5
  text "Dielectric1" at 255.684,182.06 h1.5
  text "FR-4 High Tg" at 268.551,182.06 h1.5
  text "59.20mil" at 280.062,182.06 h1.5
  text "4.8" at 289.529,182.06 h1.5
  text "3" at 249.19,179.06 h1.5
  text "Layer 2" at 255.684,179.06 h1.5
  text "CF-004" at 268.551,179.06 h1.5
  text "1.38mil" at 280.062,179.06 h1.5
  text "Dielectric 2" at 255.684,176.06 h1.5
  text "PP-006" at 268.551,176.06 h1.5
  text "2.80mil" at 280.062,176.06 h1.5
  text "4.1" at 289.529,176.06 h1.5
  text "4" at 249.19,173.06 h1.5
  text "Bottom Layer" at 255.684,173.06 h1.5
  text "2.76mil" at 280.062,173.06 h1.5
  text "Bottom Solder" at 255.684,170.06 h1.5
  text "Solder Resist" at 268.551,170.06 h1.5
  text "0.40mil" at 280.062,170.06 h1.5
  text "3.5" at 289.529,170.06 h1.5
  text "Bottom Overlay" at 255.684,167.06 h1.5
  text ".Layer_Name" at 14.656,-21.806 h1.5
M13 Component Bodies Top:
  text ".Layer_Name" at 14.656,-21.806 h1.5
M14 Component Bodies Bottom:
  text ".Layer_Name" at 14.656,-21.806 h1.5
M15 Courtyards Top:
  text ".Layer_Name" at 14.656,-21.806 h1.5
M16 Courtyards Bottom:
  text ".Layer_Name" at 14.656,-21.806 h1.5
Drill Drawing:
  circle w0.254: c136.208,61.903 r0.69
  circle w0.254: c136.208,55.69 r0.414
  circle w0.254: c136.208,55.69 r0.69
  lines w0.254: 135.517,52.584 136.208,51.893 136.898,52.584 136.208,53.274 135.517,52.584 ; 135.517,58.106 136.898,58.106 136.898,59.487 135.517,59.487 135.517,58.106 ; 135.517,65.7 136.898,65.7 136.208,64.319 135.517,65.7 ; 135.517,67.771 135.863,67.771 136.208,67.426 136.553,67.771 136.898,67.771 136.553,68.116 136.898,68.461 136.553,68.461 136.208,68.807 135.863,68.461 135.517,68.461 135.863,68.116 135.517,67.771 ; 135.517,70.878 135.863,70.878 135.863,70.532 136.553,70.532 136.553,70.878 136.898,70.878 136.898,71.568 136.553,71.568 136.553,71.913 135.863,71.913 135.863,71.568 135.517,71.568 135.517,70.878 ; 135.517,73.639 136.208,73.984 136.898,73.639 136.553,74.329 136.898,75.02 136.208,74.674 135.517,75.02 135.863,74.329 135.517,73.639 ; 135.517,78.126 136.898,78.126 136.208,76.745 135.517,78.126 ; 135.517,79.852 136.898,79.852 136.898,81.233 135.517,81.233 135.517,79.852 ; 135.517,83.304 135.863,83.304 136.208,82.959 136.553,83.304 136.898,83.304 136.553,83.649 136.898,83.994 136.553,83.994 136.208,84.339 135.863,83.994 135.517,83.994 135.863,83.649 135.517,83.304 ; 135.793,67.909 136.001,67.909 136.208,67.702 136.415,67.909 136.622,67.909 136.415,68.116 136.622,68.323 136.415,68.323 136.208,68.53 136.001,68.323 135.793,68.323 136.001,68.116 135.793,67.909 ; 135.793,77.85 136.622,77.85 136.208,77.022 135.793,77.85 ; 135.793,80.128 136.622,80.128 136.622,80.957 135.793,80.957 135.793,80.128
  lines w0.305: 134.264,50.961 215.074,50.961 ; 134.264,85.133 215.074,85.133 ; 142.714,47.855 142.714,88.24 ; 151.018,47.855 151.018,88.24 ; 166.941,47.855 166.941,88.24 ; 173.422,47.855 173.422,88.24 ; 182.806,47.855 182.806,88.24 ; 200.906,47.855 200.906,88.24 ; 134.264,47.855 215.074,47.855 215.074,88.24 134.264,88.24 134.264,47.855
  text "Symbol" at 136.128,86.065 h1.8
  text "Quantity" at 143.646,86.065 h1.8
  text "Finished Hole Size" at 151.95,86.065 h1.8
  text "Plated" at 167.873,86.065 h1.8
  text "Hole Type" at 174.354,86.065 h1.8
  text "Drill Layer Pair" at 183.738,86.065 h1.8
  text "Hole Tolerance" at 201.838,86.065 h1.8
  text "4" at 143.646,82.959 h1.5
  text "50.00mil (1.270mm)" at 151.95,82.959 h1.5
  text "NPTH" at 167.873,82.959 h1.5
  text "Round" at 174.354,82.959 h1.5
  text "Top Layer - Bottom Layer" at 183.738,82.959 h1.5
  text "2" at 143.646,79.852 h1.5
  text "59.00mil (1.499mm)" at 151.95,79.852 h1.5
  text "NPTH" at 167.873,79.852 h1.5
  text "Round" at 174.354,79.852 h1.5
  text "Top Layer - Bottom Layer" at 183.738,79.852 h1.5
  text "3" at 143.646,76.745 h1.5
  text "125.98mil (3.200mm)" at 151.95,76.745 h1.5
  text "NPTH" at 167.873,76.745 h1.5
  text "Round" at 174.354,76.745 h1.5
  text "Top Layer - Bottom Layer" at 183.738,76.745 h1.5
  text "44" at 143.646,73.639 h1.5
  text "7.87mil (0.200mm)" at 151.95,73.639 h1.5
  text "PTH" at 167.873,73.639 h1.5
  text "Round" at 174.354,73.639 h1.5
  text "Top Layer - Bottom Layer" at 183.738,73.639 h1.5
  text "636" at 143.646,70.532 h1.5
  text "11.81mil (0.300mm)" at 151.95,70.532 h1.5
  text "PTH" at 167.873,70.532 h1.5
  text "Round" at 174.354,70.532 h1.5
  text "Top Layer - Bottom Layer" at 183.738,70.532 h1.5
  text "6" at 143.646,67.426 h1.5
  text "12.99mil (0.330mm)" at 151.95,67.426 h1.5
  text "PTH" at 167.873,67.426 h1.5
  text "Round" at 174.354,67.426 h1.5
  text "Top Layer - Bottom Layer" at 183.738,67.426 h1.5
  text "2" at 143.646,64.319 h1.5
  text "33.07mil (0.840mm)" at 151.95,64.319 h1.5
  text "PTH" at 167.873,64.319 h1.5
  text "Round" at 174.354,64.319 h1.5
  text "Top Layer - Bottom Layer" at 183.738,64.319 h1.5
  text "10" at 143.646,61.213 h1.5
  text "33.07mil (0.840mm)" at 151.95,61.213 h1.5
  text "PTH" at 167.873,61.213 h1.5
  text "Round" at 174.354,61.213 h1.5
  text "Top Layer - Bottom Layer" at 183.738,61.213 h1.5
  text "30" at 143.646,58.106 h1.5
  text "35.43mil (0.900mm)" at 151.95,58.106 h1.5
  text "PTH" at 167.873,58.106 h1.5
  text "Round" at 174.354,58.106 h1.5
  text "Top Layer - Bottom Layer" at 183.738,58.106 h1.5
  text "42" at 143.646,55 h1.5
  text "40.16mil (1.020mm)" at 151.95,55 h1.5
  text "PTH" at 167.873,55 h1.5
  text "Round" at 174.354,55 h1.5
  text "Top Layer - Bottom Layer" at 183.738,55 h1.5
  text "2" at 143.646,51.893 h1.5
  text "120.00mil (3.048mm)" at 151.95,51.893 h1.5
  text "PTH" at 167.873,51.893 h1.5
  text "Round" at 174.354,51.893 h1.5
  text "Top Layer - Bottom Layer" at 183.738,51.893 h1.5
  text "781 Total" at 143.646,48.787 h1.5
  text ".Layer_Name" at 14.656,-21.806 h1.5
M17 Embedded Cavity:
  text ".Layer_Name" at 14.656,-21.806 h1.5
M18 Embedded Assembly:
  text ".Layer_Name" at 14.656,-21.806 h1.5
M19 Embedded Keepout:
  text ".Layer_Name" at 14.656,-21.806 h1.5

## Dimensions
0,-10.16 to 25.4,-10.16 on M2 Board Dimensions
0,0 to 120,0 on M2 Board Dimensions
0,0 to 0,77 on M2 Board Dimensions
